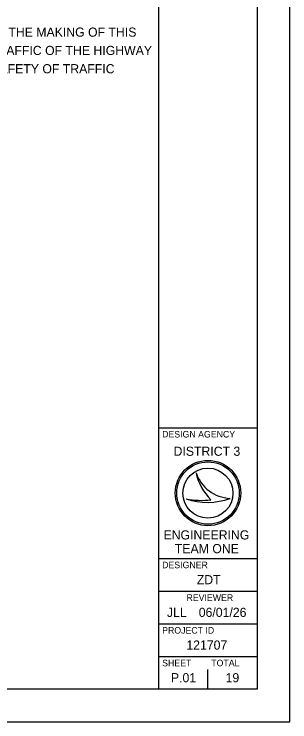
# Model space of a CAD drawing. Extents: x 0 to 34, y 0 to 22.
# Drawn here: x 29.79 to 34, y 0 to 10.83 of the extents above; entities that cross this region are included whole.
import ezdxf

# ---------------------------------------------------------------- set-up
doc = ezdxf.new("R2010")
doc.units = 0
for name, color, linetype in [('SH_Border', 7, 'Continuous'), ('SH_Cut_Line', 7, 'Continuous'), ('SH_Data', 7, 'Continuous')]:
    doc.layers.add(name, color=color, linetype=linetype)

msp = doc.modelspace()

# ---------------------------------------------------------------- linework, layer by layer
at = {"layer": 'SH_Border'}
for p, q in [((32, 0.5), (32, 21.5)), ((32, 4.5), (33.5, 4.5)), ((32, 2.5), (33.5, 2.5)), ((32, 2), (33.5, 2)), ((32, 1.5), (33.5, 1.5)), ((32, 1), (33.5, 1))]:
    msp.add_line(p, q, dxfattribs=at)
msp.add_lwpolyline([(1.5, 21.5), (33.5, 21.5), (33.5, 0.5), (1.5, 0.5)], close=True, dxfattribs=at)
at = {"layer": 'SH_Cut_Line'}
msp.add_lwpolyline([(0, 0), (34, 0), (34, 22), (0, 22)], close=True, dxfattribs=at)
at = {"layer": 'SH_Data'}
for p, q in [((32.567, 3.81), (32.567, 3.81)), ((32.75, 3.5), (32.75, 3.5)), ((32.417, 3.41), (32.417, 3.41)), ((33.087, 3.419), (33.087, 3.419)), ((32.75, 0.5), (32.75, 0.8)), ((32.375, 0.675), (32.375, 0.675))]:
    msp.add_line(p, q, dxfattribs=at)
for radius in [0.5, 0.477, 0.477, 0.382]:
    msp.add_circle((32.75, 3.5), radius, dxfattribs=at)
for centre, radius, start, end in [((33.116, 3.998), 0.58, 198.9257, 198.9319), ((33.347, 3.97), 0.796, 191.6379, 191.6421), ((33.116, 3.998), 0.58, 198.9319, 267.1657), ((33.347, 3.97), 0.796, 191.6421, 226.0947), ((32.739, 4.37), 1.013, 251.4576, 290.0832), ((32.648, 4.654), 1.266, 259.4964, 259.4995), ((32.739, 4.37), 1.013, 251.4527, 251.4576), ((32.648, 4.654), 1.266, 259.4995, 276.6672)]:
    msp.add_arc(centre, radius, start, end, dxfattribs=at)

# ---------------------------------------------------------------- texts
for s, height, p in [(' I HEREBY APPROVE THESE PLANS AND DECLARE THAT THE MAKING OF THIS', 0.14, (24.5, 10.481)), ('IMPROVEMENT WILL NOT REQUIRE THE CLOSING TO TRAFFIC OF THE HIGHWAY', 0.14, (24.5, 10.201)), ('AND THAT PROVISIONS FOR THE MAINTENANCE AND SAFETY OF TRAFFIC', 0.14, (24.5, 9.921)), ('DESIGN AGENCY', 0.1, (32.05, 4.35)), ('DISTRICT 3', 0.14, (32.224, 4.07)), ('ENGINEERING', 0.14, (32.071, 2.79)), ('TEAM ONE', 0.14, (32.244, 2.58)), ('DESIGNER', 0.1, (32.05, 2.35)), ('ZDT', 0.14, (32.579, 2.105)), ('REVIEWER', 0.1, (32.422, 1.85)), ('JLL', 0.14, (32.123, 1.605)), ('06/01/26', 0.14, (32.609, 1.605)), ('PROJECT ID', 0.1, (32.05, 1.35)), ('121707', 0.14, (32.42, 1.105)), ('SHEET', 0.1, (32.05, 0.85)), ('TOTAL', 0.1, (32.8, 0.85)), ('P.01', 0.14, (32.184, 0.605)), ('19', 0.14, (33.019, 0.605))]:
    msp.add_text(s, height=height, dxfattribs=at).set_placement(p)

doc.saveas('drawing.dxf')
